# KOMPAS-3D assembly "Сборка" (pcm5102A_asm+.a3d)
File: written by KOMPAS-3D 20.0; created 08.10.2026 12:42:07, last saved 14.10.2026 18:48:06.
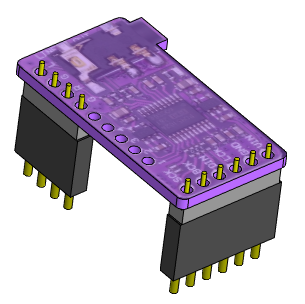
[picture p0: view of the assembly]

Document properties: Полное имя файла: D:\myProjects\Progect_esp32\box_compas\цап ацп\pcm5102A_asm+.a3d

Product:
- Part/product: Сборка
    Масса: 0.0106182
  - Component [detail]: Деталь  | Масса: 0.0012713; source file: ..\разъемы\pbs_4.m3d
  - Component [detail]: Деталь  | Масса: 0.000521406; source file: ..\разъемы\pls_4.m3d
  - Component [detail]: Деталь  | Масса: 0.00613645; source file: pcm5102A.m3d
  - Component [detail]: Деталь  | Масса: 0.00078211; source file: ..\разъемы\pls_6.m3d
  - Component [detail]: Деталь  | Масса: 0.00190694; source file: ..\разъемы\pbs_6.m3d

Referenced files in D:\myProjects\Progect_esp32\box_compas\цап ацп\: pcm5102A.m3d
Referenced files in D:\myProjects\Progect_esp32\box_compas\разъемы\: pls_6.m3d, pbs_6.m3d, pls_4.m3d, pbs_4.m3d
